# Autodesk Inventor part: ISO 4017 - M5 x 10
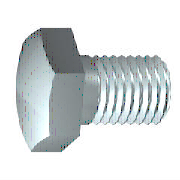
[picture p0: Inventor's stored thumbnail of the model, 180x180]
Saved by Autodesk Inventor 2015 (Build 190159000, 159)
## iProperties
Created: 2012-02
Part Number: ISO 4017 - M5 x 10
Material: Stainless Steel, 440C
Description: Hexagon head screws
Document SubType Name: Modeling
Standard: ISO 4017
Designer: 1103005
Standard Revision: Third edition 1999-08-15
Standards Organization: ISO
Language: en-US
Size Designation: M5 x 10
Categories: <MemberInstance><Categories><Category DisplayName="Fasteners" InternalName="e4da775c-781d-43d5-af7c-5136215cf5a6" Mnemonic="FSTN"><Category DisplayName="Bolts"
Density: 7.75 g/cm^3
Appearance: Semi-Polished
IsCustomPart: 1
Author: 1103005
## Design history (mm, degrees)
sketch "Sketch1"
  geometry: L1 (0, 3.44)-(0, 2.5); L2 (2.4, 2.5)-(10, 2.5); L3 (10, 2.5)-(10, 0); L4 (10, 0)-(-0.5, 0); L5 (-2.6, 0)-(12.1, 0) reference; L6 (-0.5, 0)-(-0.5, 3.44); L7 (-0.5, 3.44)-(0, 3.44); L8 (2.4, 2.5)-(1.909, 2.5); L9 (1.909, 2.5)-(0, 2.5); L10 (0, -0.688)-(0, 4.128) reference
  constraints: 16 end point, 2 collinear, 2 perpendicular, 1 parallel
  dimensions: "d0" = 10 distance between parallel lines of L3 L1 (= NLG); "d1" = 7.6 distance from line of L2.start L3 (= GEL); "d2" = 5 diameter of L2 L4 (= GD); "d9" = 0.5001 distance between parallel lines of L6 L1 (computed from SD); "d10" = 6.88 diameter of L7 L4 (= SD2); "d13" = 0.49086 distance of L2.start L8.end (computed from GAL); "d14" = 5 diameter of L9 L4 (= BDM)
revolve "Body" sketch "Sketch1" stored, may be unused: angle "d12" = 90 deg
sketch "Sketch2"
  geometry: L1 (0, 4.619)-(4, 2.309); L2 (4, 2.309)-(4, -2.309); L3 (4, -2.309)-(0, -4.619); L4 (0, -4.619)-(-4, -2.309); L5 (-4, -2.309)-(-4, 2.309); L6 (-4, 2.309)-(0, 4.619); 2 further points
  constraints: 12 end point, 1 coincident, 1 vertical, 11 other
  dimensions: "d11" = 8 distance between parallel lines of L5 L2 (= SW)
extrude "Head" join sketch "Sketch2" distance "d3" = 3 (= KOH - SD); taper "d4" = 0 deg
sketch "Sketch4"
  geometry: L1 (-3.5, 4)-(-3.5, 4.619); L2 (-3.5, 4.619)-(-3.143, 4.619); L3 (-3.143, 4.619)-(-3.5, 4); L4 (-4.1, 0)-(0.1, 0) reference; L5 (-0.5, 4.619)-(-3.5, 4.619) reference; L6 (-3.5, 2.309)-(-3.5, 4.619) reference
  constraints: 6 end point, 2 collinear, 1 perpendicular, 1 vertical
  dimensions: "d5" = 30 deg angle of L3 L1 (= ANG1); "d19" = 8 diameter of L1.start L4 (= SW0)
revolve "Chamfer1" sketch "Sketch4" stored, may be unused: angle "d21" = 90 deg
workplane "Work Plane1"
body "Solid1"
feature "Thread" dims "d15" = 7.6 (= GEL), "d16" = 0
chamfer "Chamfer2" distance "d6" = 0.49076 (= -0.5 x SPD + 0.5 x GD); stored, may be unused: second distance "d7" = 0.49086 (computed from GUL), angle "d55" = 45 deg
other parameters: "NLG" = 10 [user parameter; used in 1 equation term], "GD" = 5 (= NND) [user parameter; used in 2 equation terms], "BDM" = 5 (= NND) [user parameter; used in 1 equation term], "KOH" = 3.5 [user parameter; used in 1 equation term], "GEL" = 7.6 [user parameter; used in 2 equation terms], "SW" = 8 [user parameter; used in 2 equation terms], "SW0" = 8 (= SW) [user parameter; used in 1 equation term], "SPD" = 4.01848 (= NND - 1.2269 x PTC) [user parameter; used in 1 equation term], "SD2" = 6.88 [user parameter; used in 2 equation terms], "SD" = 0.5 [user parameter; used in 2 equation terms], "ANG1" = 30 deg [user parameter; used in 1 equation term], "GAL" = 0.49076 (= 0.61345 x PTC) [user parameter; used in 1 equation term], "GUL" = 0.49076 (= 0.61345 x PTC) [user parameter; used in 1 equation term], "d8" = 0, "RR" = 0.2 [user parameter], "d57" = 0, "d58" = 0, "TPU" = 12.5 (computed from PTC) [user parameter], "GD1" = 4.01848 (= THREADDIA - 1.2269 x PTC) [user parameter], "THREADDIA" = 5 [user parameter; used in 1 equation term], "SDH" = 6.88 (= SD2) [user parameter], "SDHG" = 2.4 [user parameter], "TOA" = 30 deg [user parameter], "PTC" = 0.8 [user parameter; used in 5 equation terms], "NND" = 5 [user parameter; used in 3 equation terms], "E0" = 9.24 [user parameter]
